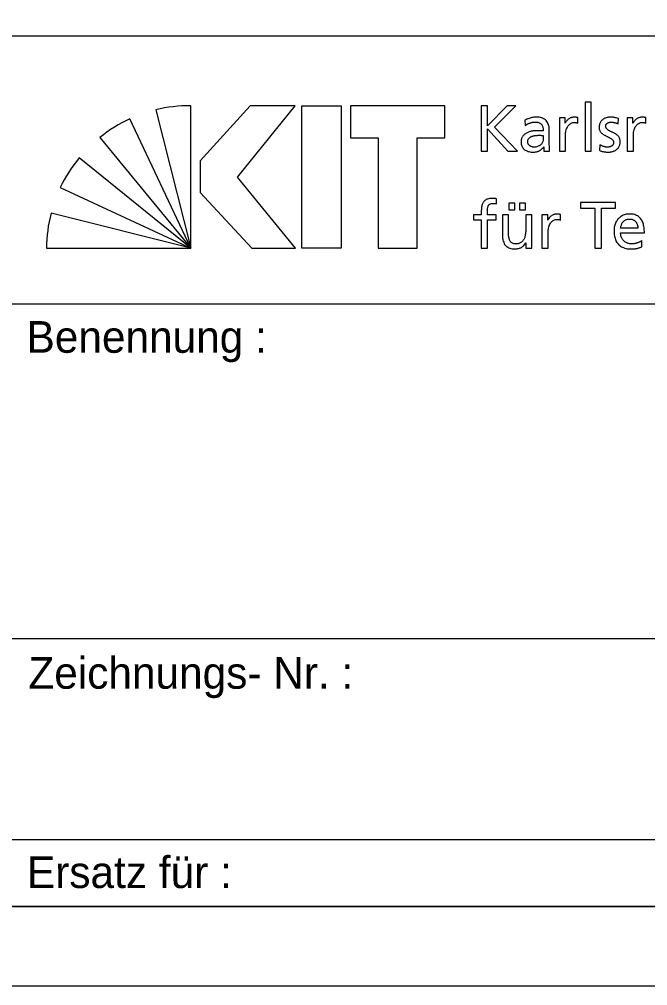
# Model space of a CAD drawing. Extents: x 0 to 119, y 0 to 84.
# Drawn here: x 110.07 to 114.03, y 0 to 6.1 of the extents above; entities that cross this region are included whole.
import ezdxf

# ---------------------------------------------------------------- set-up
doc = ezdxf.new("R2010")
doc.units = 0
doc.layers.add('90_Plankopf', color=7, linetype='Continuous')

msp = doc.modelspace()

# ---------------------------------------------------------------- linework, layer by layer
at = {"layer": '90_Plankopf'}
for p, q in [((100.612, 5.999), (118.4, 5.999)), ((100.612, 5.999), (118.4, 5.999)), ((111.1481, 4.6586), (111.1481, 5.5584)), ((112.981, 5.5586), (112.981, 5.2706)), ((110.9275, 5.5333), (111.1481, 4.6586)), ((111.1481, 4.6586), (110.7633, 5.4752)), ((113.2579, 5.4662), (113.26, 5.4332)), ((113.5926, 5.4484), (113.5926, 5.4831)), ((113.8457, 5.4439), (113.849, 5.4778)), ((114.0211, 5.4484), (114.0211, 5.4831)), ((113.4118, 5.3118), (113.4118, 5.3989)), ((110.5744, 5.3585), (111.1481, 4.6586)), ((113.373, 5.3709), (113.373, 5.3523)), ((113.7297, 5.3118), (113.7277, 5.2772)), ((112.981, 5.2706), (113.0222, 5.2706)), ((113.1506, 5.2706), (113.2108, 5.2706)), ((111.1481, 4.6586), (110.4434, 5.2286)), ((110.324, 5.0413), (111.1481, 4.6586)), ((113.0773, 4.9393), (113.079, 4.9706)), ((111.1481, 4.6586), (110.2658, 4.8788)), ((113.4827, 4.8365), (113.4827, 4.8712)), ((113.9706, 4.7841), (113.8616, 4.7841)), ((113.8616, 4.7552), (114.0119, 4.7552)), ((113.9958, 4.6673), (113.9958, 4.7061)), ((110.2364, 4.6586), (111.1481, 4.6586)), ((110.0001, 4.307), (118.4, 4.307)), ((110.0001, 2.192), (118.4, 2.192)), ((110.0001, 0.923), (118.4, 0.923)), ((118.4, 0.5), (100.612, 0.5)), ((101.78, 0.5), (118.4, 0.5)), ((101.78, 0.5), (118.4, 0.5))]:
    msp.add_line(p, q, dxfattribs=at)
for points in [[(0, 0), (118.9, 0), (118.9, 84.1), (0, 84.1)], [(2.5, 0.5), (118.4, 0.5), (118.4, 83.6), (2.5, 83.6)], [(111.8066, 5.5586), (111.5236, 5.5586), (111.2073, 5.2099), (111.2073, 5.0092), (111.5338, 4.6586), (111.8085, 4.6586), (111.4422, 5.1063)], [(112.097, 5.5586), (112.097, 4.6586), (111.8501, 4.6586), (111.8501, 5.5586)], [(112.1562, 5.5586), (112.1562, 5.356), (112.3301, 5.356), (112.3301, 4.6586), (112.5771, 4.6586), (112.5771, 5.356), (112.751, 5.356), (112.751, 5.5586)]]:
    msp.add_lwpolyline(points, close=True, dxfattribs=at)
for points in [[(113.2108, 5.2706), (113.0647, 5.4224), (113.2001, 5.5586), (113.1452, 5.5586), (113.0222, 5.4319), (113.0222, 5.5586), (112.981, 5.5586)], [(113.6381, 5.2706), (113.6768, 5.2706), (113.6768, 5.5801), (113.6381, 5.5801), (113.6381, 5.2706)], [(113.5122, 5.4484), (113.5113, 5.4484), (113.5113, 5.481), (113.475, 5.481), (113.475, 5.2706), (113.5138, 5.2706), (113.5138, 5.3663)], [(113.9407, 5.4484), (113.9398, 5.4484), (113.9398, 5.481), (113.9035, 5.481), (113.9035, 5.2706), (113.9423, 5.2706), (113.9423, 5.3663)], [(113.0222, 5.2706), (113.0222, 5.4117), (113.1506, 5.2706)], [(113.3763, 5.2978), (113.3772, 5.2978), (113.3772, 5.2706), (113.4135, 5.2706)], [(113.699, 4.6586), (113.7403, 4.6586), (113.7403, 4.9104), (113.8298, 4.9104), (113.8298, 4.9467), (113.6094, 4.9467), (113.6094, 4.9104), (113.699, 4.9104), (113.699, 4.6586)], [(112.9824, 4.8885), (112.9824, 4.8691), (112.9329, 4.8691), (112.9329, 4.8378), (112.9824, 4.8378), (112.9824, 4.6586), (113.0212, 4.6586), (113.0212, 4.8378), (113.0769, 4.8378), (113.0769, 4.8691), (113.0212, 4.8691), (113.0212, 4.8918)], [(113.1554, 4.9426), (113.1554, 4.9013), (113.1942, 4.9013), (113.1942, 4.9426), (113.1554, 4.9426)], [(113.2231, 4.9426), (113.2231, 4.9013), (113.2619, 4.9013), (113.2619, 4.9426), (113.2231, 4.9426)], [(113.1542, 4.7602), (113.1542, 4.8691), (113.1154, 4.8691), (113.1154, 4.7441)], [(113.3015, 4.6586), (113.3015, 4.8691), (113.2627, 4.8691), (113.2627, 4.7717)], [(113.4022, 4.8365), (113.4014, 4.8365), (113.4014, 4.8691), (113.3651, 4.8691), (113.3651, 4.6586), (113.4039, 4.6586), (113.4039, 4.7544)], [(113.2631, 4.6921), (113.2639, 4.6921), (113.2639, 4.6586), (113.3015, 4.6586)]]:
    msp.add_lwpolyline(points, dxfattribs=at)
for centre, start, end in [((111.1449, 4.6056), 89.80527, 103.18947), ((111.1662, 4.6118), 115.01261, 128.3968), ((111.1816, 4.6263), 140.78977, 154.17397), ((111.1891, 4.6438), 165.72225, 179.10644)]:
    msp.add_arc(centre, 0.9528, start, end, dxfattribs=at)
for points in [[(113.4118, 5.3989), (113.4119, 5.418), (113.4091, 5.4341), (113.4033, 5.447), (113.3975, 5.4599), (113.3884, 5.4696), (113.3759, 5.4762), (113.3635, 5.4827), (113.3472, 5.486), (113.3272, 5.486), (113.3138, 5.4859), (113.3014, 5.4841), (113.2898, 5.4804), (113.2782, 5.4768), (113.2676, 5.4721), (113.2579, 5.4662)], [(113.26, 5.4332), (113.2653, 5.4376), (113.2713, 5.4414), (113.2779, 5.4446), (113.2846, 5.4478), (113.2916, 5.4503), (113.299, 5.452), (113.3063, 5.4538), (113.3137, 5.4546), (113.321, 5.4546), (113.3339, 5.4546), (113.3441, 5.4526), (113.3518, 5.4485), (113.3594, 5.4444), (113.3649, 5.4383), (113.3682, 5.4302), (113.3715, 5.4219), (113.3731, 5.4118), (113.373, 5.3997)], [(113.5926, 5.4831), (113.5899, 5.4837), (113.5873, 5.4841), (113.5849, 5.4846), (113.5824, 5.485), (113.5798, 5.4854), (113.5769, 5.4856), (113.5741, 5.4859), (113.5708, 5.486), (113.567, 5.486), (113.5595, 5.4859), (113.5523, 5.4843), (113.5452, 5.4811), (113.5382, 5.4779), (113.5318, 5.4736), (113.5261, 5.4679), (113.5203, 5.4623), (113.5157, 5.4558), (113.5122, 5.4484)], [(113.5138, 5.3663), (113.5139, 5.384), (113.5163, 5.3993), (113.521, 5.4121), (113.5257, 5.4249), (113.5323, 5.4348), (113.5409, 5.4416), (113.5494, 5.4486), (113.5595, 5.4521), (113.5712, 5.4521), (113.5746, 5.4522), (113.578, 5.4519), (113.5818, 5.4514), (113.5855, 5.4509), (113.5891, 5.4499), (113.5926, 5.4484)], [(113.849, 5.4778), (113.8414, 5.4801), (113.8337, 5.482), (113.8259, 5.4836), (113.8181, 5.4851), (113.8097, 5.4859), (113.8007, 5.486), (113.7903, 5.486), (113.7805, 5.4847), (113.7716, 5.482), (113.7625, 5.4794), (113.7547, 5.4753), (113.748, 5.47), (113.7412, 5.4647), (113.7359, 5.4579), (113.7322, 5.4498), (113.7284, 5.4417), (113.7265, 5.4321), (113.7264, 5.4212), (113.7265, 5.4128), (113.7282, 5.4056), (113.7315, 5.3994), (113.7347, 5.3933), (113.7391, 5.388), (113.7445, 5.3834), (113.75, 5.379), (113.7559, 5.375), (113.7623, 5.3715), (113.7688, 5.368), (113.7753, 5.3647), (113.7817, 5.3617), (113.7882, 5.3586), (113.7942, 5.3555), (113.7995, 5.3522), (113.805, 5.349), (113.8093, 5.3454), (113.8126, 5.3413), (113.8158, 5.3373), (113.8176, 5.3325), (113.8176, 5.3271), (113.8176, 5.3215), (113.8163, 5.3167), (113.8139, 5.3128), (113.8116, 5.309), (113.8084, 5.3059), (113.8045, 5.3035), (113.8006, 5.3012), (113.7963, 5.2995), (113.7917, 5.2985), (113.7871, 5.2975), (113.7825, 5.297), (113.778, 5.297), (113.7742, 5.297), (113.7695, 5.2975), (113.7639, 5.2986), (113.7584, 5.2997), (113.7526, 5.3014), (113.7466, 5.3036), (113.7405, 5.3058), (113.735, 5.3085), (113.7297, 5.3118)], [(113.7277, 5.2772), (113.7366, 5.2726), (113.746, 5.2694), (113.7558, 5.2678), (113.7656, 5.2662), (113.7755, 5.2655), (113.7854, 5.2656), (113.7949, 5.2656), (113.804, 5.2669), (113.8127, 5.2695), (113.8215, 5.2722), (113.8293, 5.2762), (113.8363, 5.2816), (113.8431, 5.2869), (113.8487, 5.2938), (113.8527, 5.302), (113.8568, 5.3103), (113.8588, 5.32), (113.8589, 5.3312), (113.8588, 5.3408), (113.8571, 5.3489), (113.8539, 5.3556), (113.8506, 5.3622), (113.8462, 5.3679), (113.8408, 5.3726), (113.8354, 5.3772), (113.8295, 5.3811), (113.823, 5.3845), (113.8165, 5.3878), (113.8101, 5.3909), (113.8036, 5.3937), (113.7971, 5.3966), (113.7912, 5.3995), (113.7858, 5.4026), (113.7804, 5.4058), (113.776, 5.4095), (113.7727, 5.4136), (113.7695, 5.4179), (113.7678, 5.423), (113.7677, 5.4291), (113.7678, 5.4348), (113.7696, 5.4396), (113.7729, 5.4434), (113.7763, 5.4472), (113.7808, 5.45), (113.7864, 5.4519), (113.792, 5.4538), (113.7982, 5.4546), (113.8048, 5.4546), (113.8072, 5.4546), (113.8102, 5.4543), (113.8139, 5.4538), (113.8175, 5.4531), (113.8213, 5.4523), (113.8254, 5.4513), (113.8295, 5.4503), (113.8333, 5.4491), (113.8369, 5.4478), (113.8405, 5.4466), (113.8434, 5.4453), (113.8457, 5.4439)], [(114.0211, 5.4831), (114.0184, 5.4837), (114.0158, 5.4841), (114.0134, 5.4846), (114.011, 5.485), (114.0083, 5.4854), (114.0054, 5.4856), (114.0026, 5.4859), (113.9993, 5.486), (113.9955, 5.486), (113.988, 5.4859), (113.9808, 5.4843), (113.9737, 5.4811), (113.9667, 5.4779), (113.9603, 5.4736), (113.9546, 5.4679), (113.9488, 5.4623), (113.9442, 5.4558), (113.9407, 5.4484)], [(113.9423, 5.3663), (113.9424, 5.384), (113.9448, 5.3993), (113.9495, 5.4121), (113.9542, 5.4249), (113.9608, 5.4348), (113.9694, 5.4416), (113.9779, 5.4486), (113.988, 5.4521), (113.9997, 5.4521), (114.003, 5.4522), (114.0065, 5.4519), (114.0103, 5.4514), (114.014, 5.4509), (114.0175, 5.4499), (114.0211, 5.4484)], [(113.373, 5.3997), (113.368, 5.4), (113.3633, 5.4002), (113.3589, 5.4003), (113.3546, 5.4004), (113.3502, 5.4005), (113.3459, 5.4006), (113.3415, 5.4006), (113.3368, 5.4006), (113.3318, 5.4006), (113.3237, 5.4006), (113.3151, 5.3999), (113.3063, 5.3984), (113.2973, 5.397), (113.2886, 5.3947), (113.2801, 5.3914), (113.2715, 5.3881), (113.2638, 5.3838), (113.2569, 5.3785), (113.2499, 5.3731), (113.2444, 5.3665), (113.2403, 5.3588), (113.2362, 5.3509), (113.2341, 5.3418), (113.234, 5.3312), (113.2341, 5.316), (113.2374, 5.3035), (113.2439, 5.2939), (113.2504, 5.2842), (113.2594, 5.277), (113.271, 5.2724), (113.2825, 5.2679), (113.2959, 5.2656), (113.3111, 5.2656), (113.32, 5.2657), (113.328, 5.2668), (113.335, 5.2689), (113.3421, 5.2709), (113.3483, 5.2736), (113.3536, 5.2769), (113.359, 5.2802), (113.3635, 5.2837), (113.3673, 5.2874), (113.371, 5.2911), (113.3741, 5.2945), (113.3763, 5.2978)], [(113.373, 5.3523), (113.373, 5.3418), (113.3708, 5.3323), (113.3664, 5.324), (113.362, 5.3157), (113.3554, 5.3092), (113.3467, 5.3043), (113.338, 5.2995), (113.3272, 5.297), (113.3144, 5.297), (113.31, 5.297), (113.3054, 5.2978), (113.3008, 5.2992), (113.2963, 5.3007), (113.292, 5.3028), (113.2882, 5.3057), (113.2843, 5.3087), (113.2812, 5.3123), (113.2789, 5.3165), (113.2765, 5.3207), (113.2753, 5.3257), (113.2752, 5.3312), (113.2754, 5.3386), (113.2772, 5.3448), (113.2808, 5.3497), (113.2844, 5.3546), (113.2891, 5.3586), (113.2949, 5.3615), (113.3007, 5.3645), (113.3069, 5.3667), (113.3135, 5.3682), (113.3201, 5.3696), (113.3265, 5.3706), (113.3326, 5.3711), (113.3387, 5.3715), (113.3439, 5.3717), (113.3483, 5.3717), (113.3524, 5.3717), (113.3565, 5.3715), (113.3607, 5.3713), (113.3648, 5.3711), (113.3689, 5.3709), (113.373, 5.3709)], [(113.4135, 5.2706), (113.4132, 5.2726), (113.4129, 5.2753), (113.4126, 5.2787), (113.4125, 5.2821), (113.4122, 5.2865), (113.4121, 5.2919), (113.4119, 5.2973), (113.4118, 5.3039), (113.4118, 5.3118)], [(113.079, 4.9706), (113.0751, 4.9712), (113.071, 4.9719), (113.0668, 4.9723), (113.0625, 4.9728), (113.0579, 4.9731), (113.053, 4.9731), (113.0388, 4.973), (113.027, 4.971), (113.0178, 4.9671), (113.0086, 4.9631), (113.0014, 4.9574), (112.9962, 4.95), (112.991, 4.9426), (112.9875, 4.9337), (112.9854, 4.9233), (112.9833, 4.9129), (112.9824, 4.9014), (112.9824, 4.8885)], [(113.0212, 4.8918), (113.0212, 4.899), (113.0216, 4.9056), (113.0224, 4.9116), (113.0232, 4.9177), (113.0249, 4.923), (113.0275, 4.9275), (113.03, 4.932), (113.0338, 4.9355), (113.0388, 4.9379), (113.0439, 4.9404), (113.0505, 4.9417), (113.0588, 4.9417), (113.0621, 4.9417), (113.0655, 4.9415), (113.0688, 4.9411), (113.0722, 4.9407), (113.075, 4.9401), (113.0773, 4.9393)], [(113.4827, 4.8712), (113.48, 4.8717), (113.4774, 4.8722), (113.475, 4.8727), (113.4725, 4.8731), (113.4698, 4.8734), (113.467, 4.8737), (113.4642, 4.8739), (113.4609, 4.874), (113.4571, 4.874), (113.4496, 4.874), (113.4423, 4.8724), (113.4352, 4.8692), (113.4282, 4.866), (113.4218, 4.8616), (113.4161, 4.856), (113.4104, 4.8503), (113.4057, 4.8439), (113.4022, 4.8365)], [(113.4039, 4.7544), (113.4039, 4.7721), (113.4064, 4.7873), (113.411, 4.8001), (113.4158, 4.8129), (113.4224, 4.8228), (113.431, 4.8297), (113.4395, 4.8367), (113.4496, 4.8401), (113.4612, 4.8402), (113.4646, 4.8403), (113.4681, 4.84), (113.4718, 4.8395), (113.4756, 4.8389), (113.4791, 4.8379), (113.4827, 4.8365)], [(114.0119, 4.7552), (114.0119, 4.7722), (114.0103, 4.788), (114.0072, 4.8023), (114.0041, 4.8168), (113.9989, 4.8293), (113.9918, 4.84), (113.9846, 4.8507), (113.9751, 4.8591), (113.9631, 4.865), (113.9512, 4.8709), (113.9365, 4.874), (113.919, 4.874), (113.9041, 4.874), (113.8906, 4.8714), (113.8785, 4.8662), (113.8665, 4.861), (113.8561, 4.8537), (113.8474, 4.8442), (113.8387, 4.8347), (113.8321, 4.8235), (113.8275, 4.8105), (113.8228, 4.7976), (113.8205, 4.7833), (113.8204, 4.7676), (113.8204, 4.7504), (113.8225, 4.7348), (113.8269, 4.7209), (113.8312, 4.7069), (113.8379, 4.695), (113.8469, 4.685), (113.8558, 4.6749), (113.8671, 4.6672), (113.8808, 4.6619), (113.8945, 4.6564), (113.9107, 4.6538), (113.9293, 4.6537), (113.9408, 4.6538), (113.9506, 4.6545), (113.9587, 4.656), (113.9667, 4.6575), (113.9737, 4.6593), (113.9797, 4.6614), (113.9855, 4.6634), (113.9909, 4.6654), (113.9958, 4.6673)], [(113.8616, 4.7841), (113.8623, 4.791), (113.8639, 4.7978), (113.8664, 4.8047), (113.8688, 4.8116), (113.8722, 4.8179), (113.8768, 4.8236), (113.8812, 4.8294), (113.8869, 4.8339), (113.8937, 4.8374), (113.9006, 4.8408), (113.9087, 4.8426), (113.9182, 4.8427), (113.9266, 4.8426), (113.934, 4.8411), (113.9404, 4.8381), (113.947, 4.835), (113.9524, 4.8309), (113.9569, 4.8255), (113.9614, 4.8201), (113.9648, 4.8139), (113.9671, 4.8069), (113.9694, 4.7998), (113.9706, 4.7922), (113.9706, 4.7841)], [(113.2627, 4.7717), (113.2627, 4.7589), (113.2615, 4.7471), (113.2589, 4.7365), (113.2564, 4.726), (113.2525, 4.7169), (113.2473, 4.7092), (113.2421, 4.7015), (113.2354, 4.6956), (113.2273, 4.6914), (113.2193, 4.6872), (113.2097, 4.6851), (113.1987, 4.685), (113.1875, 4.6857), (113.1786, 4.6889), (113.1721, 4.6945), (113.1656, 4.7002), (113.161, 4.7084), (113.1582, 4.7193), (113.1554, 4.7302), (113.1541, 4.7438), (113.1542, 4.7602)], [(113.1154, 4.7441), (113.1154, 4.7251), (113.1181, 4.709), (113.1237, 4.6955), (113.1293, 4.682), (113.1379, 4.6717), (113.1496, 4.6645), (113.1612, 4.6574), (113.1761, 4.6538), (113.1942, 4.6537), (113.204, 4.6538), (113.2135, 4.6553), (113.2225, 4.6583), (113.2315, 4.6614), (113.2396, 4.6658), (113.2466, 4.6715), (113.2537, 4.6772), (113.2592, 4.6841), (113.2631, 4.6921)], [(113.9958, 4.7061), (113.9933, 4.7041), (113.9899, 4.7019), (113.9852, 4.6995), (113.9806, 4.6971), (113.9754, 4.6948), (113.9694, 4.6926), (113.9634, 4.6904), (113.9572, 4.6886), (113.9506, 4.6872), (113.944, 4.6858), (113.9374, 4.6851), (113.9309, 4.685), (113.9217, 4.6851), (113.913, 4.6868), (113.9046, 4.6902), (113.8964, 4.6935), (113.8889, 4.6983), (113.8825, 4.7045), (113.8761, 4.7107), (113.871, 4.7181), (113.8673, 4.7267), (113.8636, 4.7353), (113.8617, 4.7448), (113.8616, 4.7552)]]:
    msp.add_open_spline(points, degree=3, dxfattribs=at)

# ---------------------------------------------------------------- texts
for s, p in [('Benennung :', (110.1113, 3.9979)), ('Zeichnungs- Nr. :', (110.1227, 1.8758)), ('Ersatz für :', (110.1139, 0.6169))]:
    msp.add_text(s, height=0.2, dxfattribs=at).set_placement(p)

doc.saveas('drawing.dxf')
